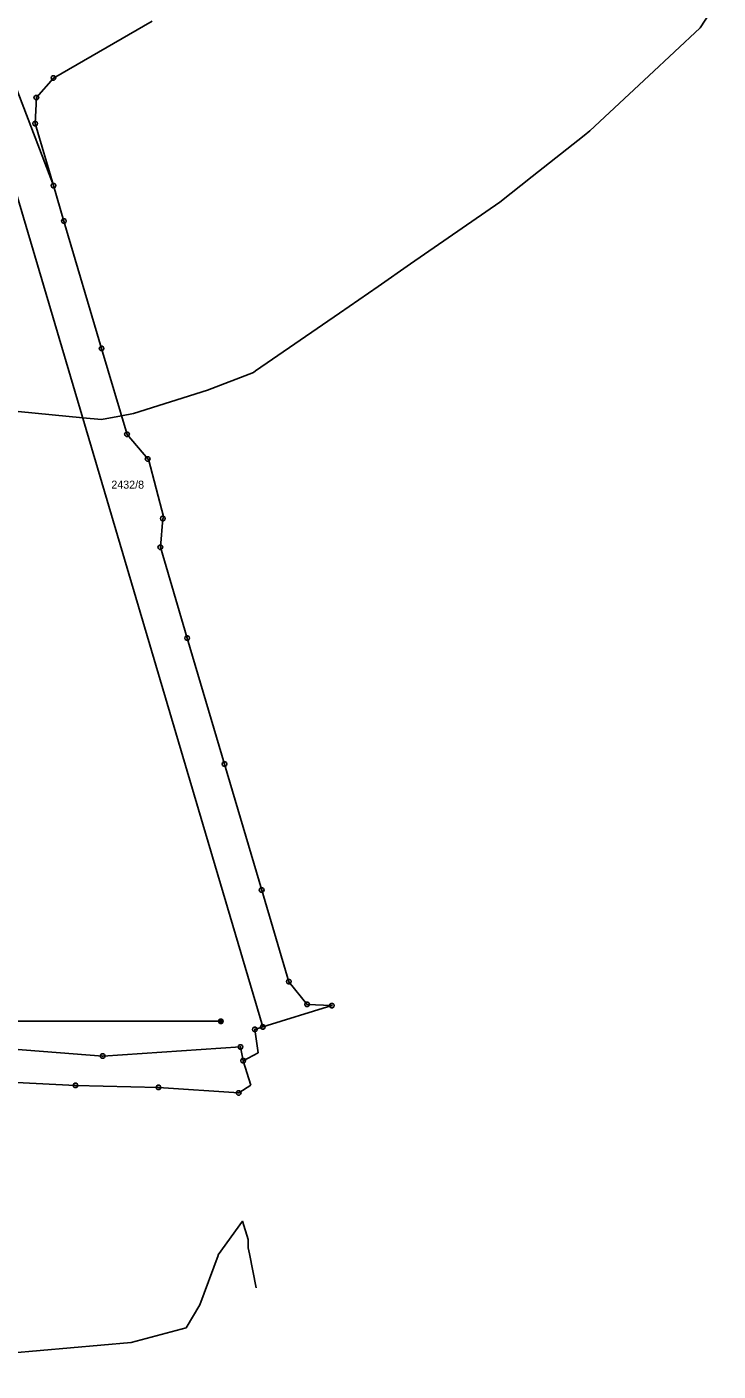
# Model space of a CAD drawing. Extents: x -760611 to -758411, y -1176479 to -1174807.
# Drawn here: x -758625.1 to -758478.3, y -1175325.4 to -1175039.9 of the extents above; entities that cross this region are included whole.
import ezdxf

# ---------------------------------------------------------------- set-up
doc = ezdxf.new("R2010")
doc.units = 0
for name, color, linetype in [('1', 7, 'Continuous'), ('11', 7, 'Continuous'), ('2', 7, 'Continuous'), ('6', 7, 'Continuous'), ('8', 7, 'Continuous')]:
    doc.layers.add(name, color=color, linetype=linetype)

msp = doc.modelspace()

# ---------------------------------------------------------------- linework, layer by layer
at = {"layer": '1'}
for p, q in [((-758632.02, -1175040.71), (-758619.42, -1175073.66)), ((-758619.44, -1175050.8), (-758598.46, -1175038.72)), ((-758623.06, -1175054.97), (-758619.44, -1175050.8)), ((-758623.31, -1175060.49), (-758623.06, -1175054.97)), ((-758619.42, -1175073.66), (-758623.31, -1175060.49)), ((-758587.13, -1175211.17), (-758630.01, -1175066.05)), ((-758617.2, -1175081.18), (-758619.42, -1175073.66)), ((-758609.21, -1175108.24), (-758617.2, -1175081.18)), ((-758603.81, -1175126.47), (-758609.21, -1175108.24)), ((-758599.42, -1175131.7), (-758603.81, -1175126.47)), ((-758599.28, -1175131.71), (-758599.42, -1175131.7)), ((-758599.28, -1175131.71), (-758596, -1175144.18)), ((-758596.73, -1175150.46), (-758596.19, -1175144.35)), ((-758596.19, -1175144.35), (-758596, -1175144.18)), ((-758596.73, -1175150.46), (-758591.03, -1175169.74)), ((-758583.12, -1175196.49), (-758591.03, -1175169.74)), ((-758575.22, -1175223.24), (-758583.12, -1175196.49)), ((-758574.97, -1175252.32), (-758587.13, -1175211.17)), ((-758569.47, -1175242.7), (-758575.22, -1175223.24)), ((-758565.59, -1175247.52), (-758569.47, -1175242.7)), ((-758574.97, -1175252.32), (-758560.34, -1175247.78)), ((-758560.34, -1175247.78), (-758565.59, -1175247.52)), ((-758576.67, -1175252.85), (-758574.97, -1175252.32)), ((-758608.97, -1175258.5), (-758659.81, -1175254.52)), ((-758575.95, -1175257.83), (-758576.67, -1175252.85)), ((-758579.71, -1175256.56), (-758608.97, -1175258.5)), ((-758579.15, -1175259.49), (-758579.71, -1175256.56)), ((-758579.15, -1175259.49), (-758575.95, -1175257.83)), ((-758577.56, -1175264.68), (-758579.15, -1175259.49)), ((-758661.68, -1175262.32), (-758614.76, -1175264.74)), ((-758614.76, -1175264.74), (-758597.14, -1175265.17)), ((-758597.14, -1175265.17), (-758580.11, -1175266.34)), ((-758580.11, -1175266.34), (-758577.56, -1175264.68))]:
    msp.add_line(p, q, dxfattribs=at)
at = {"layer": '11'}
for points in [[(-758478.33, -1175034.26), (-758482.16, -1175040.17), (-758493.03, -1175050.33), (-758505.56, -1175062.05), (-758506.76, -1175063), (-758517.8, -1175071.73), (-758524.7, -1175077.19), (-758543.61, -1175090.27), (-758550.53, -1175095.06), (-758558.71, -1175100.72), (-758576.52, -1175113), (-758576.98, -1175113.32), (-758586.75, -1175117.08), (-758602.46, -1175122.08), (-758604.98, -1175122.54), (-758609.25, -1175123.32), (-758613.2, -1175122.93), (-758673.25, -1175117.07)], [(-758658.74, -1175325.4), (-758658.59, -1175320.08), (-758628.72, -1175321.59), (-758602.92, -1175319.32), (-758591.26, -1175316.24), (-758588.35, -1175311.33), (-758584.49, -1175300.82), (-758584.43, -1175300.74), (-758579.33, -1175293.56), (-758578.06, -1175297.48), (-758578.1, -1175299.22), (-758577.84, -1175300.51), (-758576.42, -1175307.68)]]:
    msp.add_lwpolyline(points, dxfattribs=at)
at = {"layer": '6'}
msp.add_line((-758583.89, -1175251.11), (-758658.17, -1175251.04), dxfattribs=at)
msp.add_lwpolyline([(-758584.04, -1175250.63), (-758583.73, -1175250.63), (-758583.48, -1175250.81), (-758583.38, -1175251.1), (-758583.48, -1175251.39), (-758583.73, -1175251.57), (-758584.04, -1175251.57), (-758584.29, -1175251.39), (-758584.39, -1175251.1), (-758584.29, -1175250.81), (-758584.04, -1175250.63), (-758584.01, -1175250.67), (-758583.77, -1175250.67), (-758583.61, -1175250.75), (-758584.17, -1175250.75), (-758584.25, -1175250.83), (-758583.53, -1175250.83), (-758583.53, -1175250.91), (-758584.25, -1175250.91), (-758584.29, -1175250.99), (-758583.49, -1175250.99), (-758583.45, -1175251.07), (-758584.33, -1175251.07), (-758584.33, -1175251.15), (-758583.45, -1175251.15), (-758583.48, -1175251.23), (-758584.29, -1175251.23), (-758584.28, -1175251.31), (-758583.47, -1175251.31), (-758583.52, -1175251.39), (-758584.24, -1175251.39), (-758584.16, -1175251.47), (-758583.6, -1175251.47), (-758583.71, -1175251.55), (-758584.05, -1175251.55)], dxfattribs=at)
at = {"layer": '8'}
for p, q in [((-758619.56, -1175050.8), (-758619.32, -1175050.8)), ((-758623.18, -1175054.97), (-758622.94, -1175054.97)), ((-758623.43, -1175060.49), (-758623.19, -1175060.49)), ((-758619.54, -1175073.66), (-758619.3, -1175073.66)), ((-758617.32, -1175081.18), (-758617.08, -1175081.18)), ((-758609.33, -1175108.24), (-758609.09, -1175108.24)), ((-758603.93, -1175126.47), (-758603.69, -1175126.47)), ((-758599.54, -1175131.7), (-758599.3, -1175131.7)), ((-758596.31, -1175144.35), (-758596.07, -1175144.35)), ((-758596.85, -1175150.46), (-758596.61, -1175150.46)), ((-758591.15, -1175169.74), (-758590.91, -1175169.74)), ((-758583.24, -1175196.49), (-758583, -1175196.49)), ((-758575.34, -1175223.24), (-758575.1, -1175223.24)), ((-758569.59, -1175242.7), (-758569.35, -1175242.7)), ((-758565.71, -1175247.52), (-758565.47, -1175247.52)), ((-758560.46, -1175247.78), (-758560.22, -1175247.78)), ((-758575.09, -1175252.32), (-758574.85, -1175252.32)), ((-758576.79, -1175252.85), (-758576.55, -1175252.85)), ((-758579.83, -1175256.56), (-758579.59, -1175256.56)), ((-758609.09, -1175258.5), (-758608.85, -1175258.5)), ((-758579.27, -1175259.49), (-758579.03, -1175259.49)), ((-758614.88, -1175264.74), (-758614.64, -1175264.74)), ((-758597.26, -1175265.17), (-758597.02, -1175265.17)), ((-758580.23, -1175266.34), (-758579.99, -1175266.34))]:
    msp.add_line(p, q, dxfattribs=at)
for points in [[(-758619.29, -1175050.32), (-758619.04, -1175050.5), (-758618.94, -1175050.79), (-758619.04, -1175051.08), (-758619.29, -1175051.26), (-758619.6, -1175051.26), (-758619.85, -1175051.08), (-758619.95, -1175050.79), (-758619.85, -1175050.5), (-758619.6, -1175050.32)], [(-758622.91, -1175054.49), (-758622.66, -1175054.67), (-758622.56, -1175054.96), (-758622.66, -1175055.25), (-758622.91, -1175055.43), (-758623.22, -1175055.43), (-758623.47, -1175055.25), (-758623.57, -1175054.96), (-758623.47, -1175054.67), (-758623.22, -1175054.49)], [(-758623.16, -1175060.01), (-758622.91, -1175060.19), (-758622.81, -1175060.48), (-758622.91, -1175060.77), (-758623.16, -1175060.95), (-758623.47, -1175060.95), (-758623.72, -1175060.77), (-758623.82, -1175060.48), (-758623.72, -1175060.19), (-758623.47, -1175060.01)], [(-758619.27, -1175073.18), (-758619.02, -1175073.36), (-758618.92, -1175073.65), (-758619.02, -1175073.94), (-758619.27, -1175074.12), (-758619.58, -1175074.12), (-758619.83, -1175073.94), (-758619.93, -1175073.65), (-758619.83, -1175073.36), (-758619.58, -1175073.18)], [(-758617.05, -1175080.7), (-758616.8, -1175080.88), (-758616.7, -1175081.17), (-758616.8, -1175081.46), (-758617.05, -1175081.64), (-758617.36, -1175081.64), (-758617.61, -1175081.46), (-758617.71, -1175081.17), (-758617.61, -1175080.88), (-758617.36, -1175080.7)], [(-758609.06, -1175107.76), (-758608.81, -1175107.94), (-758608.71, -1175108.23), (-758608.81, -1175108.52), (-758609.06, -1175108.7), (-758609.37, -1175108.7), (-758609.62, -1175108.52), (-758609.72, -1175108.23), (-758609.62, -1175107.94), (-758609.37, -1175107.76)], [(-758603.66, -1175125.99), (-758603.41, -1175126.17), (-758603.31, -1175126.46), (-758603.41, -1175126.75), (-758603.66, -1175126.93), (-758603.97, -1175126.93), (-758604.22, -1175126.75), (-758604.32, -1175126.46), (-758604.22, -1175126.17), (-758603.97, -1175125.99)], [(-758599.27, -1175131.22), (-758599.02, -1175131.4), (-758598.92, -1175131.69), (-758599.02, -1175131.98), (-758599.27, -1175132.16), (-758599.58, -1175132.16), (-758599.83, -1175131.98), (-758599.93, -1175131.69), (-758599.83, -1175131.4), (-758599.58, -1175131.22)], [(-758596.04, -1175143.87), (-758595.79, -1175144.05), (-758595.69, -1175144.34), (-758595.79, -1175144.63), (-758596.04, -1175144.81), (-758596.35, -1175144.81), (-758596.6, -1175144.63), (-758596.7, -1175144.34), (-758596.6, -1175144.05), (-758596.35, -1175143.87)], [(-758596.58, -1175149.98), (-758596.33, -1175150.16), (-758596.23, -1175150.45), (-758596.33, -1175150.74), (-758596.58, -1175150.92), (-758596.89, -1175150.92), (-758597.14, -1175150.74), (-758597.24, -1175150.45), (-758597.14, -1175150.16), (-758596.89, -1175149.98)], [(-758590.88, -1175169.26), (-758590.63, -1175169.44), (-758590.53, -1175169.73), (-758590.63, -1175170.02), (-758590.88, -1175170.2), (-758591.19, -1175170.2), (-758591.44, -1175170.02), (-758591.54, -1175169.73), (-758591.44, -1175169.44), (-758591.19, -1175169.26)], [(-758582.97, -1175196.01), (-758582.72, -1175196.19), (-758582.62, -1175196.48), (-758582.72, -1175196.77), (-758582.97, -1175196.95), (-758583.28, -1175196.95), (-758583.53, -1175196.77), (-758583.63, -1175196.48), (-758583.53, -1175196.19), (-758583.28, -1175196.01)], [(-758575.07, -1175222.76), (-758574.82, -1175222.94), (-758574.72, -1175223.23), (-758574.82, -1175223.52), (-758575.07, -1175223.7), (-758575.38, -1175223.7), (-758575.63, -1175223.52), (-758575.73, -1175223.23), (-758575.63, -1175222.94), (-758575.38, -1175222.76)], [(-758569.32, -1175242.22), (-758569.07, -1175242.4), (-758568.97, -1175242.69), (-758569.07, -1175242.98), (-758569.32, -1175243.16), (-758569.63, -1175243.16), (-758569.88, -1175242.98), (-758569.98, -1175242.69), (-758569.88, -1175242.4), (-758569.63, -1175242.22)], [(-758565.44, -1175247.04), (-758565.19, -1175247.22), (-758565.09, -1175247.51), (-758565.19, -1175247.8), (-758565.44, -1175247.98), (-758565.75, -1175247.98), (-758566, -1175247.8), (-758566.1, -1175247.51), (-758566, -1175247.22), (-758565.75, -1175247.04)], [(-758560.19, -1175247.3), (-758559.94, -1175247.48), (-758559.84, -1175247.77), (-758559.94, -1175248.06), (-758560.19, -1175248.24), (-758560.5, -1175248.24), (-758560.75, -1175248.06), (-758560.85, -1175247.77), (-758560.75, -1175247.48), (-758560.5, -1175247.3)], [(-758576.52, -1175252.37), (-758576.27, -1175252.55), (-758576.17, -1175252.84), (-758576.27, -1175253.13), (-758576.52, -1175253.31), (-758576.83, -1175253.31), (-758577.08, -1175253.13), (-758577.18, -1175252.84), (-758577.08, -1175252.55), (-758576.83, -1175252.37)], [(-758574.82, -1175251.84), (-758574.57, -1175252.02), (-758574.47, -1175252.31), (-758574.57, -1175252.6), (-758574.82, -1175252.78), (-758575.13, -1175252.78), (-758575.38, -1175252.6), (-758575.48, -1175252.31), (-758575.38, -1175252.02), (-758575.13, -1175251.84)], [(-758608.82, -1175258.02), (-758608.57, -1175258.2), (-758608.47, -1175258.49), (-758608.57, -1175258.78), (-758608.82, -1175258.96), (-758609.13, -1175258.96), (-758609.38, -1175258.78), (-758609.48, -1175258.49), (-758609.38, -1175258.2), (-758609.13, -1175258.02)], [(-758579.56, -1175256.08), (-758579.31, -1175256.26), (-758579.21, -1175256.55), (-758579.31, -1175256.84), (-758579.56, -1175257.02), (-758579.87, -1175257.02), (-758580.12, -1175256.84), (-758580.22, -1175256.55), (-758580.12, -1175256.26), (-758579.87, -1175256.08)], [(-758579, -1175259.01), (-758578.75, -1175259.19), (-758578.65, -1175259.48), (-758578.75, -1175259.77), (-758579, -1175259.95), (-758579.31, -1175259.95), (-758579.56, -1175259.77), (-758579.66, -1175259.48), (-758579.56, -1175259.19), (-758579.31, -1175259.01)], [(-758614.61, -1175264.26), (-758614.36, -1175264.44), (-758614.26, -1175264.73), (-758614.36, -1175265.02), (-758614.61, -1175265.2), (-758614.92, -1175265.2), (-758615.17, -1175265.02), (-758615.27, -1175264.73), (-758615.17, -1175264.44), (-758614.92, -1175264.26)], [(-758596.99, -1175264.69), (-758596.74, -1175264.87), (-758596.64, -1175265.16), (-758596.74, -1175265.45), (-758596.99, -1175265.63), (-758597.3, -1175265.63), (-758597.55, -1175265.45), (-758597.65, -1175265.16), (-758597.55, -1175264.87), (-758597.3, -1175264.69)], [(-758579.96, -1175265.86), (-758579.71, -1175266.04), (-758579.61, -1175266.33), (-758579.71, -1175266.62), (-758579.96, -1175266.8), (-758580.27, -1175266.8), (-758580.52, -1175266.62), (-758580.62, -1175266.33), (-758580.52, -1175266.04), (-758580.27, -1175265.86)]]:
    msp.add_lwpolyline(points, close=True, dxfattribs=at)

# ---------------------------------------------------------------- texts
at = {"layer": '2'}
msp.add_text('2432/8', height=1.7, dxfattribs=at).set_placement((-758607.15, -1175138))

doc.saveas('drawing.dxf')
